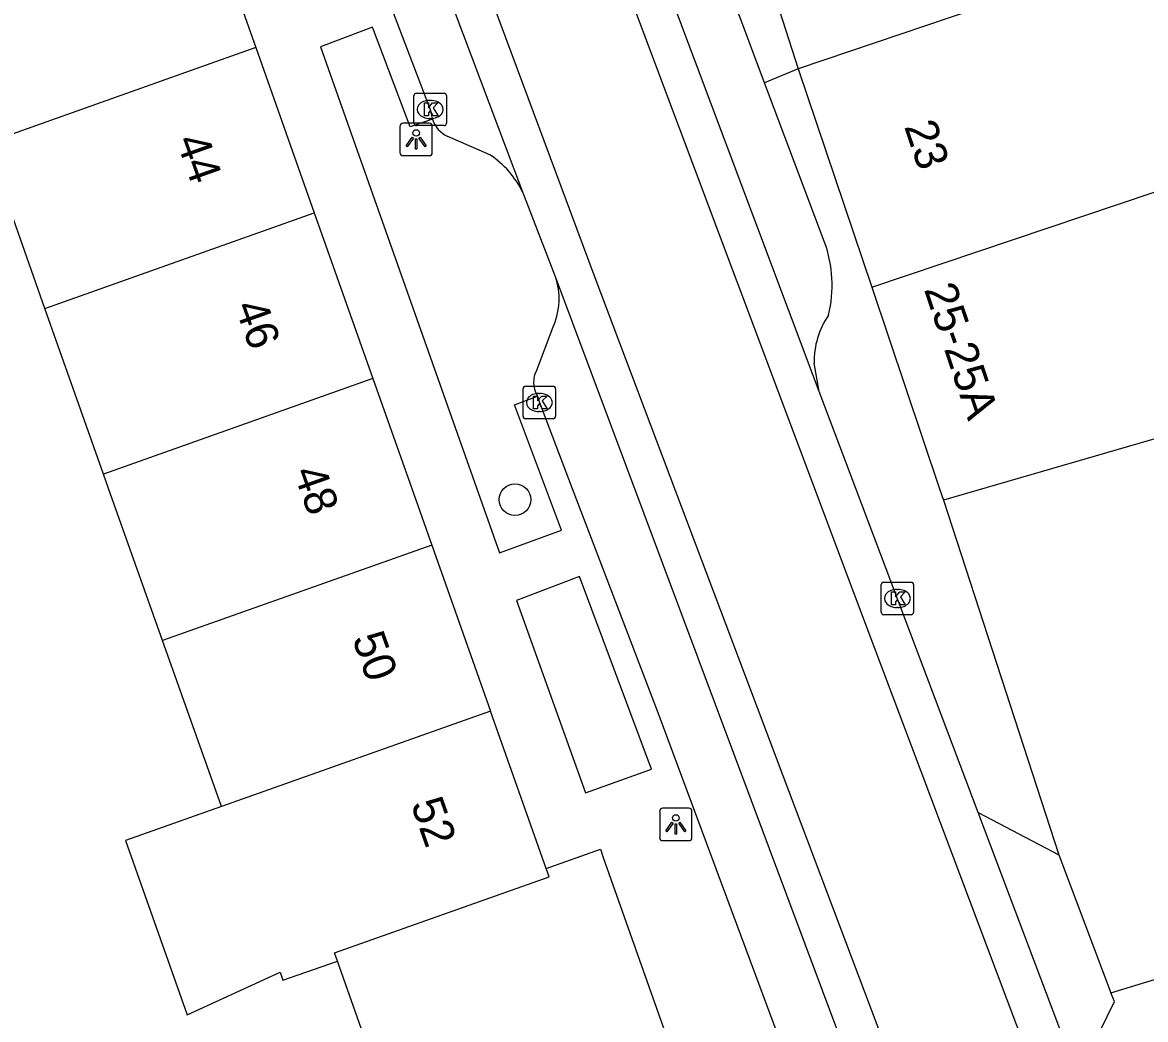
# Model space of a CAD drawing. Extents: x 159377 to 159983, y 382996 to 383595.
# Drawn here: x 159705.78 to 159740.41, y 383233.64 to 383264.36 of the extents above; entities that cross this region are included whole.
import ezdxf

# ---------------------------------------------------------------- set-up
doc = ezdxf.new("R2010")
doc.units = 0
for name, color, linetype in [('IMGEO_Boom', 7, 'Continuous'), ('IMGEO_Kolk', 7, 'Continuous'), ('IMGEO_Lichtpunt', 7, 'Continuous'), ('IMGEO_Pand', 7, 'Continuous'), ('IMGEO_Pand_nummerreeks', 7, 'Continuous'), ('IMGEO_Parkeervlak_gesloten', 7, 'Continuous'), ('IMGEO_Parkeervlak_open', 7, 'Continuous'), ('IMGEO_Rijbaan_lokaal_gesloten', 7, 'Continuous'), ('IMGEO_Voetpad_open', 7, 'Continuous')]:
    doc.layers.add(name, color=color, linetype=linetype)

msp = doc.modelspace()

# ---------------------------------------------------------------- linework, layer by layer
at = {"layer": 'IMGEO_Boom'}
msp.add_circle((159720.969, 383249.658), 0.489, dxfattribs=at)
at = {"layer": 'IMGEO_Kolk'}
for p, q in [((159717.855, 383261.258), (159717.855, 383262.11)), ((159717.93, 383262.184), (159718.782, 383262.184)), ((159718.343, 383261.964), (159718.368, 383261.964)), ((159718.856, 383262.11), (159718.856, 383261.258)), ((159718.366, 383261.404), (159718.341, 383261.404)), ((159718.782, 383261.184), (159717.93, 383261.184)), ((159721.219, 383252.226), (159721.219, 383253.078)), ((159721.294, 383253.152), (159722.146, 383253.152)), ((159721.707, 383252.932), (159721.732, 383252.932)), ((159722.22, 383253.078), (159722.22, 383252.226)), ((159721.73, 383252.372), (159721.705, 383252.372)), ((159722.146, 383252.152), (159721.294, 383252.152)), ((159732.259, 383246.187), (159732.259, 383247.039)), ((159732.334, 383247.113), (159733.186, 383247.113)), ((159733.26, 383247.039), (159733.26, 383246.187)), ((159732.747, 383246.893), (159732.772, 383246.893)), ((159732.77, 383246.333), (159732.745, 383246.333)), ((159733.186, 383246.113), (159732.334, 383246.113))]:
    msp.add_line(p, q, dxfattribs=at)
for points in [[(159717.855, 383261.258), (159717.855, 383262.11)], [(159717.93, 383262.184), (159718.782, 383262.184)], [(159718.856, 383262.11), (159718.856, 383261.258)], [(159718.176, 383261.884), (159718.299, 383261.884), (159718.299, 383261.733), (159718.429, 383261.884), (159718.593, 383261.884), (159718.447, 383261.733), (159718.6, 383261.484), (159718.448, 383261.484), (159718.363, 383261.648), (159718.299, 383261.581), (159718.299, 383261.484), (159718.176, 383261.484), (159718.176, 383261.884)], [(159718.782, 383261.184), (159717.93, 383261.184)], [(159721.219, 383252.226), (159721.219, 383253.078)], [(159721.294, 383253.152), (159722.146, 383253.152)], [(159722.22, 383253.078), (159722.22, 383252.226)], [(159721.54, 383252.852), (159721.663, 383252.852), (159721.663, 383252.701), (159721.793, 383252.852), (159721.957, 383252.852), (159721.811, 383252.701), (159721.964, 383252.452), (159721.812, 383252.452), (159721.727, 383252.616), (159721.663, 383252.549), (159721.663, 383252.452), (159721.54, 383252.452), (159721.54, 383252.852)], [(159722.146, 383252.152), (159721.294, 383252.152)], [(159732.259, 383246.187), (159732.259, 383247.039)], [(159732.334, 383247.113), (159733.186, 383247.113)], [(159733.26, 383247.039), (159733.26, 383246.187)], [(159732.58, 383246.813), (159732.703, 383246.813), (159732.703, 383246.662), (159732.833, 383246.813), (159732.997, 383246.813), (159732.851, 383246.662), (159733.004, 383246.413), (159732.852, 383246.413), (159732.767, 383246.577), (159732.703, 383246.51), (159732.703, 383246.413), (159732.58, 383246.413), (159732.58, 383246.813)], [(159733.186, 383246.113), (159732.334, 383246.113)]]:
    msp.add_lwpolyline(points, dxfattribs=at)
for centre, start, end in [((159717.932, 383262.108), 91.552, 178.448), ((159717.932, 383262.108), 91.552, 178.448), ((159718.78, 383262.108), 1.552, 88.448), ((159718.78, 383262.108), 1.552, 88.448), ((159717.932, 383261.26), 181.552, 268.448), ((159717.932, 383261.26), 181.552, 268.448), ((159718.78, 383261.26), 271.552, 358.448), ((159718.78, 383261.26), 271.552, 358.448), ((159721.296, 383253.076), 91.552, 178.448), ((159721.296, 383253.076), 91.552, 178.448), ((159722.144, 383253.076), 1.552, 88.448), ((159722.144, 383253.076), 1.552, 88.448), ((159721.296, 383252.228), 181.552, 268.448), ((159721.296, 383252.228), 181.552, 268.448), ((159722.144, 383252.228), 271.552, 358.448), ((159722.144, 383252.228), 271.552, 358.448), ((159732.336, 383247.037), 91.552, 178.448), ((159732.336, 383247.037), 91.552, 178.448), ((159733.184, 383247.037), 1.552, 88.448), ((159733.184, 383247.037), 1.552, 88.448), ((159732.336, 383246.189), 181.552, 268.448), ((159732.336, 383246.189), 181.552, 268.448), ((159733.184, 383246.189), 271.552, 358.448), ((159733.184, 383246.189), 271.552, 358.448)]:
    msp.add_arc(centre, 0.0765, start, end, dxfattribs=at)
for centre, major_axis, ratio, start_param, end_param in [((159718.342, 383261.684), (-0.387, 0.002), 0.722429, 4.712389, 7.853982), ((159718.367, 383261.684), (-0.39, 0.002), 0.717154, 1.570796, 4.712389), ((159721.706, 383252.652), (-0.387, 0.002), 0.722429, 4.712389, 7.853982), ((159721.731, 383252.652), (-0.39, 0.002), 0.717154, 1.570796, 4.712389), ((159732.746, 383246.613), (-0.387, 0.002), 0.722429, 4.712389, 7.853982), ((159732.771, 383246.613), (-0.39, 0.002), 0.717154, 1.570796, 4.712389)]:
    msp.add_ellipse(centre, major_axis=major_axis, ratio=ratio, start_param=start_param, end_param=end_param, dxfattribs=at)
at = {"layer": 'IMGEO_Lichtpunt'}
for p, q in [((159718.325, 383261.256), (159717.517, 383261.256)), ((159718.325, 383261.256), (159717.517, 383261.256)), ((159717.423, 383261.161), (159717.423, 383260.354)), ((159717.423, 383261.161), (159717.423, 383260.354)), ((159718.419, 383260.354), (159718.419, 383261.161)), ((159718.419, 383260.354), (159718.419, 383261.161)), ((159717.517, 383260.26), (159718.325, 383260.26)), ((159717.517, 383260.26), (159718.325, 383260.26)), ((159726.332, 383240.146), (159725.524, 383240.146)), ((159726.332, 383240.146), (159725.524, 383240.146)), ((159725.43, 383240.051), (159725.43, 383239.244)), ((159725.43, 383240.051), (159725.43, 383239.244)), ((159726.426, 383239.244), (159726.426, 383240.051)), ((159726.426, 383239.244), (159726.426, 383240.051)), ((159725.524, 383239.15), (159726.332, 383239.15)), ((159725.524, 383239.15), (159726.332, 383239.15))]:
    msp.add_line(p, q, dxfattribs=at)
for points in [[(159717.797, 383260.825), (159717.836, 383260.797), (159717.648, 383260.535), (159717.61, 383260.562), (159717.797, 383260.825)], [(159717.899, 383260.777), (159717.946, 383260.777), (159717.946, 383260.455), (159717.899, 383260.455), (159717.899, 383260.777)], [(159718.009, 383260.797), (159718.047, 383260.824), (159718.234, 383260.562), (159718.195, 383260.534), (159718.009, 383260.797)], [(159725.804, 383239.715), (159725.843, 383239.687), (159725.655, 383239.425), (159725.617, 383239.452), (159725.804, 383239.715)], [(159725.906, 383239.667), (159725.953, 383239.667), (159725.953, 383239.345), (159725.906, 383239.345), (159725.906, 383239.667)], [(159726.016, 383239.687), (159726.054, 383239.714), (159726.241, 383239.452), (159726.202, 383239.424), (159726.016, 383239.687)]]:
    msp.add_lwpolyline(points, dxfattribs=at)
for centre in [(159717.922, 383260.959), (159725.929, 383239.849)]:
    msp.add_circle(centre, 0.0994, dxfattribs=at)
for centre, start, end in [((159717.517, 383261.161), 90, 180), ((159717.517, 383261.161), 90, 180), ((159718.325, 383261.161), 0, 90), ((159718.325, 383261.161), 0, 90), ((159717.517, 383260.354), 180, 270), ((159717.517, 383260.354), 180, 270), ((159718.325, 383260.354), 270, 0), ((159718.325, 383260.354), 270, 360), ((159725.524, 383240.051), 90, 180), ((159725.524, 383240.051), 90, 180), ((159726.332, 383240.051), 0, 90), ((159726.332, 383240.051), 0, 90), ((159725.524, 383239.244), 180, 270), ((159725.524, 383239.244), 180, 270), ((159726.332, 383239.244), 270, 0), ((159726.332, 383239.244), 270, 360)]:
    msp.add_arc(centre, 0.0946, start, end, dxfattribs=at)
at = {"layer": 'IMGEO_Pand'}
for points in [[(159711.174, 383268.697), (159712.978, 383263.595)], [(159743.947, 383260.236), (159743.531, 383261.474), (159745.86, 383262.098), (159746.219, 383260.757), (159751.409, 383262.148), (159750.66, 383264.941), (159743.051, 383262.901), (159741.795, 383266.635), (159740.025, 383266.04), (159737.433, 383265.168), (159737.321, 383265.5), (159734.445, 383264.533), (159729.705, 383262.938)], [(159712.978, 383263.595), (159704.676, 383260.641)], [(159712.978, 383263.595), (159714.782, 383258.494)], [(159729.705, 383262.938), (159731.97, 383256.207)], [(159706.477, 383255.548), (159704.676, 383260.641)], [(159731.97, 383256.207), (159743.947, 383260.236)], [(159706.477, 383255.548), (159714.782, 383258.494)], [(159714.782, 383258.494), (159716.587, 383253.394)], [(159731.97, 383256.207), (159734.059, 383249.995), (159734.178, 383249.639)], [(159708.282, 383250.447), (159706.477, 383255.548)], [(159752.884, 383255.064), (159734.178, 383249.639)], [(159716.587, 383253.394), (159708.282, 383250.447)], [(159716.587, 383253.394), (159717.787, 383250), (159718.404, 383248.254)], [(159710.1, 383245.317), (159708.44, 383249.998), (159708.282, 383250.447)], [(159718.404, 383248.254), (159710.1, 383245.317)], [(159718.404, 383248.254), (159720.212, 383243.144)], [(159711.915, 383240.202), (159710.1, 383245.317)], [(159720.212, 383243.144), (159711.915, 383240.202)], [(159721.927, 383238.295), (159720.212, 383243.144)], [(159711.915, 383240.202), (159708.956, 383239.153), (159710.862, 383233.779), (159713.727, 383235.094), (159713.815, 383234.845), (159715.495, 383235.439)], [(159721.927, 383238.295), (159723.601, 383238.887), (159723.693, 383238.627), (159729.154, 383223.187), (159726.872, 383222.38), (159727.399, 383221.102)], [(159715.495, 383235.439), (159715.407, 383235.689), (159722.019, 383238.034), (159721.927, 383238.295)], [(159717.297, 383219.92), (159720.617, 383221.086), (159720.407, 383221.68), (159719.192, 383221.25), (159719.13, 383221.427), (159720.346, 383221.857), (159717.291, 383230.493), (159716.036, 383230.049), (159715.949, 383230.293), (159717.163, 383230.722), (159715.495, 383235.439)]]:
    msp.add_lwpolyline(points, dxfattribs=at)
at = {"layer": 'IMGEO_Parkeervlak_gesloten'}
msp.add_lwpolyline([(159720.195, 383260.284), (159718.897, 383260.852)], dxfattribs=at)
for centre, radius, start, end in [((159719.275, 383261.669), 0.9, 198.658, 245.1846), ((159718.608, 383257.871), 2.888, 25.9144, 56.6756)]:
    msp.add_arc(centre, radius, start, end, dxfattribs=at)
at = {"layer": 'IMGEO_Parkeervlak_open'}
for points in [[(159721.641, 383253.652), (159722.145, 383254.988)], [(159721.659, 383252.847), (159721.65, 383252.876)]]:
    msp.add_lwpolyline(points, dxfattribs=at)
for centre, radius, start, end in [((159720.191, 383255.855), 2.138, 336.0866, 18.3335), ((159722.306, 383253.272), 0.766, 150.2424, 211.0865)]:
    msp.add_arc(centre, radius, start, end, dxfattribs=at)
at = {"layer": 'IMGEO_Rijbaan_lokaal_gesloten'}
for points in [[(159710.368, 383306.187), (159709.181, 383305.793), (159710.779, 383301.727), (159718.83, 383280.315), (159731.432, 383246.746), (159741.434, 383220.181), (159750.886, 383194.867), (159754.445, 383184.488), (159756.378, 383179.374), (159756.663, 383178.738), (159756.932, 383178.059), (159757.185, 383177.335), (159757.431, 383176.547), (159757.602, 383175.943), (159757.778, 383175.278), (159758.222, 383173.46), (159758.611, 383171.87), (159758.936, 383170.653), (159759.158, 383169.891), (159759.386, 383169.177), (159759.619, 383168.506), (159759.862, 383167.864), (159764.778, 383154.386)], [(159730.348, 383252.993), (159710.368, 383306.187)], [(159761.692, 383153.309), (159756.491, 383167.459), (159756.285, 383168.079), (159756.086, 383168.744), (159755.886, 383169.472), (159755.67, 383170.327), (159755.202, 383172.274), (159754.831, 383173.7), (159754.417, 383175.141), (159753.971, 383176.559), (159753.48, 383178.004), (159751.397, 383183.638), (159746.908, 383194.293), (159734.857, 383226.26), (159723.406, 383256.576), (159713.205, 383283.99), (159705.436, 383304.551), (159704.228, 383304.153)], [(159721.206, 383259.133), (159704.228, 383304.153)], [(159722.22, 383256.527), (159721.206, 383259.133)], [(159733.753, 383225.718), (159722.22, 383256.527)], [(159735.251, 383240.012), (159731.479, 383250), (159730.348, 383252.993)], [(159738.326, 383231.879), (159735.251, 383240.012)]]:
    msp.add_lwpolyline(points, dxfattribs=at)
at = {"layer": 'IMGEO_Voetpad_open'}
for points in [[(159703.96, 383302.861), (159703.513, 383301.93), (159703.479, 383301.171), (159703.559, 383300.908), (159705.532, 383295.785), (159712.289, 383277.365), (159716.543, 383266.423), (159718.357, 383261.684), (159718.413, 383261.409), (159718.422, 383261.381)], [(159729.021, 383265.042), (159729.705, 383262.938)], [(159728.665, 383262.501), (159727.743, 383264.944)], [(159718.422, 383261.381), (159717.741, 383261.15), (159716.579, 383264.22), (159714.968, 383263.61), (159720.495, 383248.015), (159722.408, 383248.714), (159720.95, 383252.583), (159721.659, 383252.847)], [(159729.705, 383262.938), (159728.665, 383262.501)], [(159730.515, 383257.594), (159728.665, 383262.501)], [(159730.348, 383252.993), (159730.19, 383253.862)], [(159721.659, 383252.847), (159721.72, 383252.652), (159722.734, 383250), (159725.373, 383243.094), (159730.93, 383228.152)], [(159734.178, 383249.639), (159737.741, 383238.716)], [(159725.176, 383241.356), (159722.96, 383247.286), (159721.014, 383246.55), (159723.145, 383240.619), (159725.176, 383241.356)], [(159735.251, 383240.012), (159737.741, 383238.716)], [(159737.741, 383238.716), (159739.343, 383234.457)], [(159739.343, 383234.457), (159741.794, 383235.213), (159742.302, 383233.863)], [(159738.326, 383231.879), (159739.453, 383234.188), (159739.343, 383234.457)]]:
    msp.add_lwpolyline(points, dxfattribs=at)
for centre, radius, start, end in [((159726.79, 383256.266), 3.955, 346.5358, 19.6235), ((159732.747, 383253.902), 2.557, 145.6337, 180.8899)]:
    msp.add_arc(centre, radius, start, end, dxfattribs=at)

# ---------------------------------------------------------------- texts
at = {"layer": 'IMGEO_Pand_nummerreeks'}
for s, rotation, p in [('23', 288.598, (159732.962, 383261.159)), ('44', 289.4804, (159710.513, 383260.729)), ('25-25A', 288.5865, (159733.574, 383256.142)), ('46', 289.4796, (159712.321, 383255.615)), ('48', 289.4686, (159714.129, 383250.508)), ('50', 289.4796, (159715.94, 383245.383)), ('52', 289.4804, (159717.748, 383240.277))]:
    msp.add_text(s, height=1, rotation=rotation, dxfattribs=at).set_placement(p)

doc.saveas('drawing.dxf')
